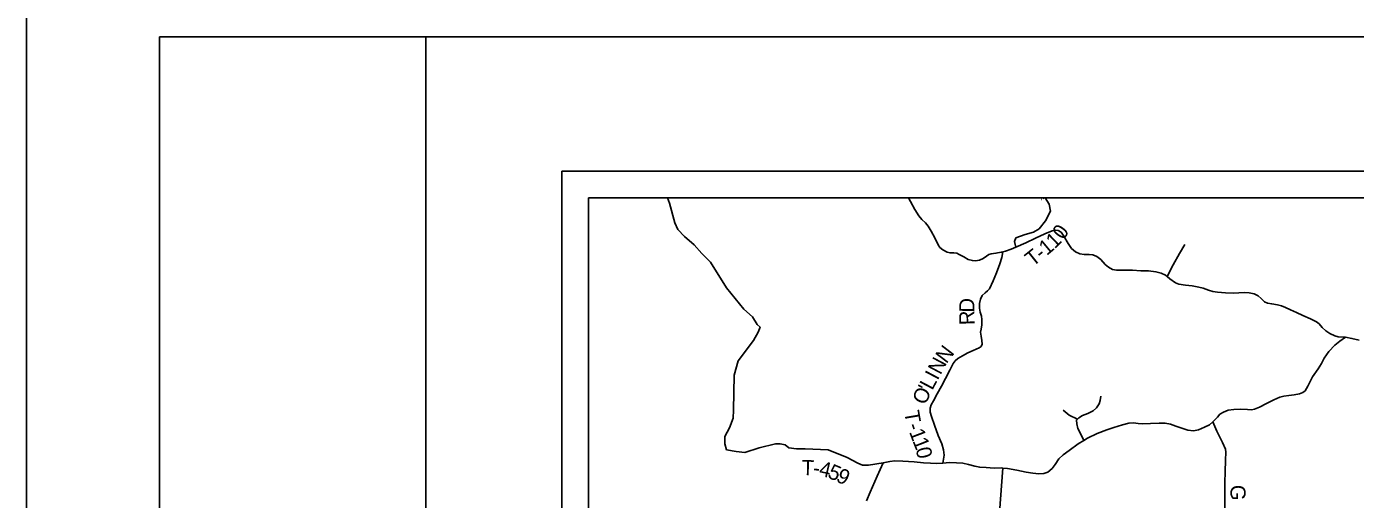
# Model space of a CAD drawing. Extents: x -84548 to 2262448, y -162180 to 525962.
# Drawn here: x 0 to 26368, y 104330 to 113725 of the extents above; entities that cross this region are included whole.
import ezdxf

# ---------------------------------------------------------------- set-up
doc = ezdxf.new("R2010")
doc.units = 0
for name, color, linetype in [('GM_X_Adjacent_County', 7, 'Continuous'), ('GM_X_County', 7, 'Continuous'), ('GM_X_Minor_Lake', 7, 'Continuous'), ('GM_X_Minor_River_Text', 7, 'Continuous'), ('GM_X_State_Route', 7, 'Continuous'), ('GM_X_Township', 7, 'Continuous'), ('GM_X_Township_Road', 7, 'Continuous'), ('GM_X_Township_ROW', 7, 'Continuous')]:
    doc.layers.add(name, color=color, linetype=linetype)

msp = doc.modelspace()

# ---------------------------------------------------------------- linework, layer by layer
at = {"layer": 'GM_X_Adjacent_County'}
for points in [[(2640, 113520), (7920, 113520), (7920, 2640), (2640, 2640)], [(7920, 113520), (176880, 113520), (176880, 2640), (7920, 2640)]]:
    msp.add_lwpolyline(points, close=True, dxfattribs=at)
at = {"layer": 'GM_X_County'}
for p, q in [((10619, 110849), (47579, 110849)), ((10619, 110849), (10619, 73889)), ((11147, 110321), (11147, 92849)), ((11147, 110321), (45035, 110321))]:
    msp.add_line(p, q, dxfattribs=at)
at = {"layer": 'GM_X_Minor_Lake'}
for points in [[(17000, 105060), (16704, 105013), (16590, 105013), (16495, 105051), (16286, 105166), (15906, 105318), (15450, 105337), (15279, 105337), (15126, 105356), (15050, 105413), (14955, 105432), (14860, 105432), (14537, 105356), (14252, 105261), (14081, 105280), (13891, 105318), (13853, 105432), (13853, 105584), (13948, 105755), (14024, 105945), (14027, 106102), (14043, 106801), (14119, 107086), (14423, 107485), (14518, 107656), (14556, 107751), (14499, 107808), (14404, 107960), (14233, 108112), (13891, 108531), (13568, 109044), (13397, 109215), (13245, 109386), (13055, 109557), (12922, 109690), (12865, 109823), (12759, 110214), (12718, 110321)], [(17498, 110321), (17537, 110246), (17624, 110089), (17707, 109963), (17762, 109894), (17835, 109827), (17893, 109756), (17953, 109659), (18021, 109526), (18090, 109389), (18125, 109336), (18182, 109289), (18267, 109241), (18325, 109228), (18397, 109227), (18457, 109223), (18504, 109199), (18595, 109147), (18682, 109099), (18768, 109076), (18830, 109070), (18912, 109083), (18983, 109119), (19048, 109166), (19096, 109199), (19141, 109210), (19235, 109222), (19339, 109240), (19369, 109248), (19426, 109264), (19537, 109304), (19628, 109344), (19825, 109426), (20019, 109518), (20205, 109606), (20351, 109669), (20415, 109680), (20469, 109671), (20528, 109637), (20579, 109561), (20666, 109417), (20734, 109318), (20812, 109250), (20902, 109211), (20989, 109197), (21087, 109197), (21155, 109192), (21239, 109158), (21317, 109095), (21402, 109001), (21470, 108944), (21550, 108898), (21629, 108887), (21759, 108884), (21780, 108884)], [(19628, 109344), (19605, 109457), (19633, 109527), (19814, 109597), (19982, 109639), (20094, 109709), (20220, 109863), (20317, 110058), (20290, 110198), (20210, 110321)], [(18184, 105052), (18209, 105207), (18193, 105319), (18162, 105434), (18091, 105599), (18013, 105806), (17955, 105979), (17932, 106065), (17932, 106141), (17953, 106209), (17999, 106289), (18070, 106426), (18153, 106580), (18236, 106730), (18323, 106898), (18388, 107032), (18427, 107086), (18476, 107129), (18573, 107183), (18679, 107242), (18780, 107290), (18903, 107342), (18941, 107369), (18960, 107416), (18956, 107488), (18943, 107577), (18931, 107651), (18942, 107712), (18952, 107802), (18956, 107904), (18948, 107972), (18925, 108054), (18911, 108128), (18911, 108224), (18926, 108306), (18964, 108381), (19019, 108432), (19070, 108474), (19107, 108516), (19182, 108670), (19249, 108832), (19311, 109011), (19349, 109136), (19369, 109248)], [(21780, 108884), (21780, 108884), (21943, 108882), (22109, 108875), (22263, 108870), (22411, 108853), (22511, 108827), (22600, 108783), (22631, 108759), (22688, 108714), (22801, 108632), (22866, 108608), (22994, 108588), (23130, 108571), (23261, 108547), (23349, 108529), (23452, 108489), (23540, 108459), (23631, 108447), (23789, 108432), (23945, 108429), (24053, 108437), (24174, 108443), (24259, 108437), (24357, 108415), (24438, 108375), (24501, 108320), (24564, 108259), (24623, 108230), (24707, 108214), (24823, 108194), (24902, 108175), (24982, 108141), (25083, 108097), (25198, 108043), (25323, 107986), (25480, 107917), (25596, 107861), (25648, 107818), (25710, 107745), (25779, 107678), (25862, 107630), (25957, 107580), (26027, 107561), (26174, 107551)], [(23777, 104160), (23776, 104395), (23776, 104665), (23785, 104879), (23790, 105110), (23799, 105270), (23791, 105326), (23728, 105462), (23617, 105690), (23536, 105874)], [(19226, 101853), (19232, 101981), (19156, 102285), (19270, 102666), (19289, 103806), (19373, 104953)]]:
    msp.add_lwpolyline(points, dxfattribs=at)
at = {"layer": 'GM_X_Minor_River_Text'}
msp.add_lwpolyline([(16666, 104301), (16739, 104472), (16878, 104791), (17000, 105060), (17128, 105084), (17232, 105095), (17390, 105092), (17612, 105078), (17796, 105061), (17938, 105048), (18054, 105046), (18172, 105051), (18184, 105052), (18311, 105062), (18451, 105060), (18577, 105049), (18691, 105027), (18819, 104994), (18914, 104970), (19038, 104963), (19199, 104955), (19339, 104956), (19373, 104953), (19467, 104944), (19649, 104913), (19834, 104874), (19970, 104850), (20086, 104837), (20187, 104843), (20265, 104872), (20349, 104942), (20410, 105027), (20486, 105135), (20571, 105220), (20689, 105306), (20866, 105432), (20981, 105502), (21053, 105547), (21243, 105640), (21438, 105713), (21576, 105759), (21748, 105812), (21873, 105843), (21965, 105851), (22057, 105842), (22147, 105834), (22301, 105839), (22475, 105849), (22591, 105846), (22701, 105824), (22807, 105787), (22921, 105745), (23043, 105704), (23153, 105696), (23255, 105711), (23375, 105765), (23471, 105816), (23536, 105874), (23630, 105965), (23677, 106023), (23749, 106067), (23845, 106104), (23957, 106120), (24083, 106121), (24225, 106116), (24305, 106110), (24364, 106124), (24466, 106165), (24606, 106238), (24747, 106312), (24867, 106365), (24949, 106385), (25045, 106398), (25152, 106410), (25256, 106427), (25326, 106453), (25368, 106487), (25425, 106584), (25518, 106763), (25626, 106923), (25693, 107030), (25748, 107140), (25840, 107271), (25961, 107398), (26061, 107478), (26174, 107551), (26298, 107531), (26440, 107494)], dxfattribs=at)
at = {"layer": 'GM_X_State_Route'}
msp.add_line((20186, 110301), (20168, 110321), dxfattribs=at)
msp.add_lwpolyline([(20134, 110288), (20136, 110289)], dxfattribs=at)
at = {"layer": 'GM_X_Township'}
msp.add_lwpolyline([(0, 0), (179520, 0), (179520, 116160), (0, 116160)], close=True, dxfattribs=at)
at = {"layer": 'GM_X_Township_ROW'}
for points in [[(22631, 108759), (22752, 108994), (22877, 109213), (22984, 109393)], [(20981, 105502), (20917, 105628), (20863, 105743), (20837, 105834), (20833, 105908), (20854, 105928), (20879, 105951), (20954, 105999), (21059, 106039), (21166, 106093), (21230, 106149), (21285, 106228), (21301, 106298), (21316, 106385)], [(20854, 105928), (20688, 106008), (20566, 106105)]]:
    msp.add_lwpolyline(points, dxfattribs=at)

# ---------------------------------------------------------------- texts
at = {"layer": 'GM_X_Township_Road'}
for s, rotation, p in [('0', 54.6454, (20572, 109473)), ('1', 39.7739, (20241, 109164)), ('1', 44.2443, (20402, 109299)), ('T', 38.5484, (19964, 108943)), ('-', 38.7842, (20140, 109083)), ('D', 88.9217, (18805, 108040)), ('R', 91.741, (18812, 107798)), ('N', 52.56, (18251, 107014)), ('N', 61.9384, (18134, 106792)), ('I', 62.1017, (18076, 106684)), ('O', 65.2215, (17832, 106191)), ("'", 62.2001, (17941, 106427)), ('L', 62.1047, (17971, 106485)), ('T', 279.7801, (17412, 106072)), ('-', 289.1641, (17464, 105799)), ('1', 290.8135, (17508, 105674)), ('1', 291.6543, (17575, 105496)), ('0', 282.8093, (17640, 105336)), ('T', 358.4077, (15378, 104816)), ('4', 347.255, (15710, 104806)), ('5', 337.4086, (15877, 104770)), ('-', 357.2982, (15601, 104810)), ('9', 333.5979, (16043, 104701)), ('G', 270.0328, (23889, 104620))]:
    msp.add_text(s, height=300, rotation=rotation, dxfattribs=at).set_placement(p)

doc.saveas('drawing.dxf')
